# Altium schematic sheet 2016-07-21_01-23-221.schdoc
size 342 x 120 mm; SheetNumber: 1; SheetTotal: 1
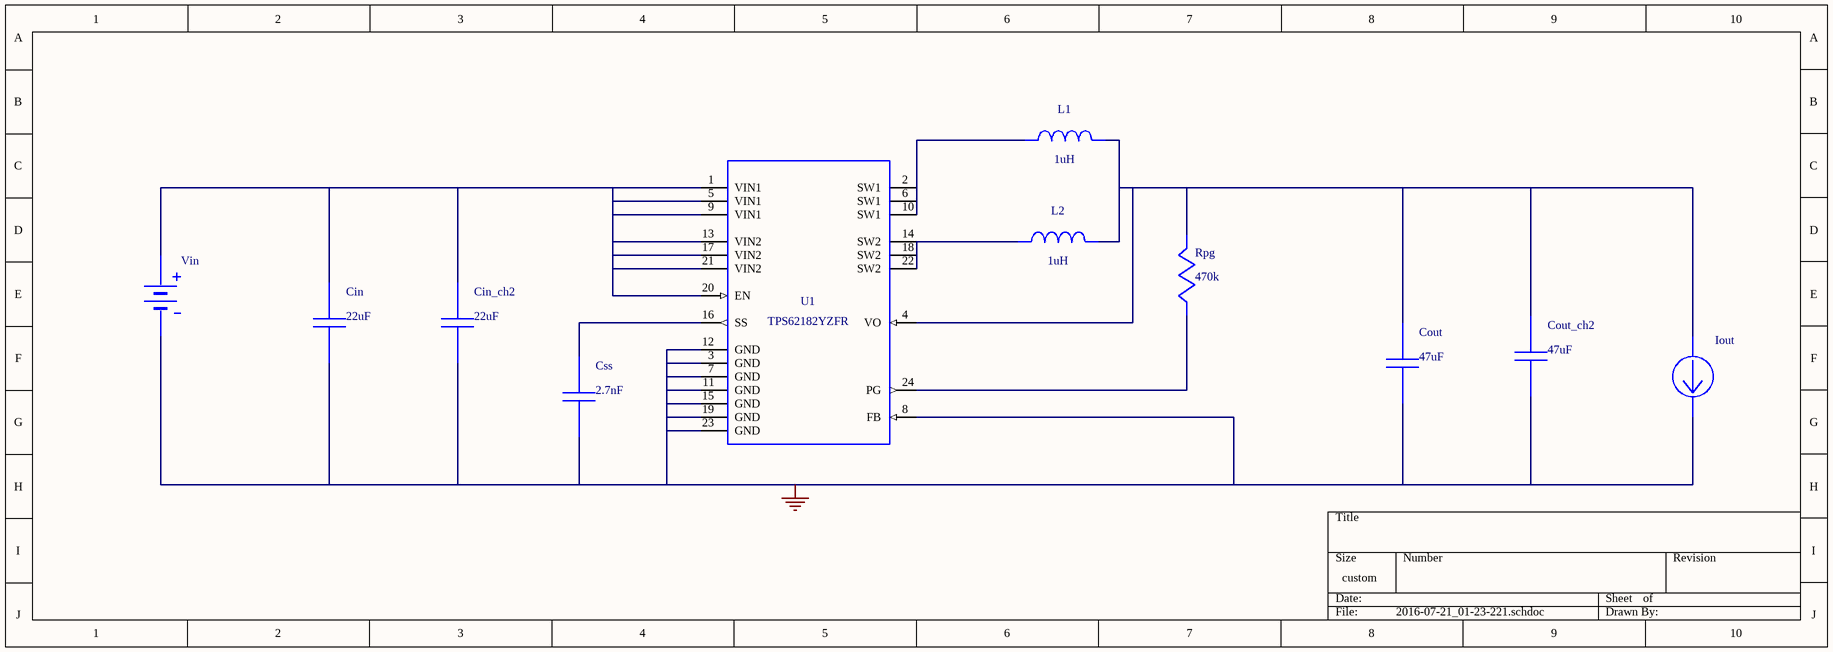
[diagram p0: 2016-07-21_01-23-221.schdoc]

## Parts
Cin  value 22uF  (hidden comment: C3225X6S1C226M)
Cin_ch2  value 22uF  (hidden comment: C3225X6S1C226M)
Cout  value 47uF  (hidden comment: GRM31CC80J476KE18L)
Cout_ch2  value 47uF  (hidden comment: GRM31CC80J476KE18L)
Css  value 2.7nF  (hidden comment: GRM188R71E272KA01D)
Iout  WB_CURRENT_LOAD  (value not drawn)
L1  value 1uH  (hidden comment: MLP2012S1R0MT0S1)
L2  value 1uH  (hidden comment: MLP2012S1R0MT0S1)
Rpg  value 470k  (hidden comment: RC0603FR-07470KL)
U1  TPS62182YZFR
Vin  WB_BATTERY  (value not drawn)

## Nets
0: Cin.2 Cin_ch2.2 Cout.2 Cout_ch2.2 Css.2 Iout.2(-) U1.3(GND) U1.7(GND) U1.8(FB) U1.11(GND) U1.12(GND) U1.15(GND) U1.19(GND) U1.23(GND) Vin.2(-)
NetCin_1: Cin.1 Cin_ch2.1 U1.1(VIN1) U1.5(VIN1) U1.9(VIN1) U1.13(VIN2) U1.17(VIN2) U1.20(EN) U1.21(VIN2) Vin.1(+)
NetCout_1: Cout.1 Cout_ch2.1 Iout.1(+) L1.2 L2.2 Rpg.1 U1.4(VO)
NetCss_1: Css.1 U1.16(SS)
NetL1_1: L1.1 U1.2(SW1) U1.6(SW1) U1.10(SW1)
NetL2_1: L2.1 U1.14(SW2) U1.18(SW2) U1.22(SW2)
NetRpg_2: Rpg.2 U1.24(PG)

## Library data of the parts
Cin Cin_ch2 = C3225X6S1C226M: Manufacturer Name: TDK
Cout Cout_ch2 = GRM31CC80J476KE18L: GRM31CC80J476KE1; Manufacturer Name: MuRata
Css = GRM188R71E272KA01D: GRM188R71E272KA0; Manufacturer Name: MuRata
L1 L2 = MLP2012S1R0MT0S1: Unknown; Manufacturer Name: TDK
Rpg = RC0603FR-07470KL: Manufacturer Name: Yageo America
U1 = TPS62182YZFR: Manufacturer Name: Texas Instruments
